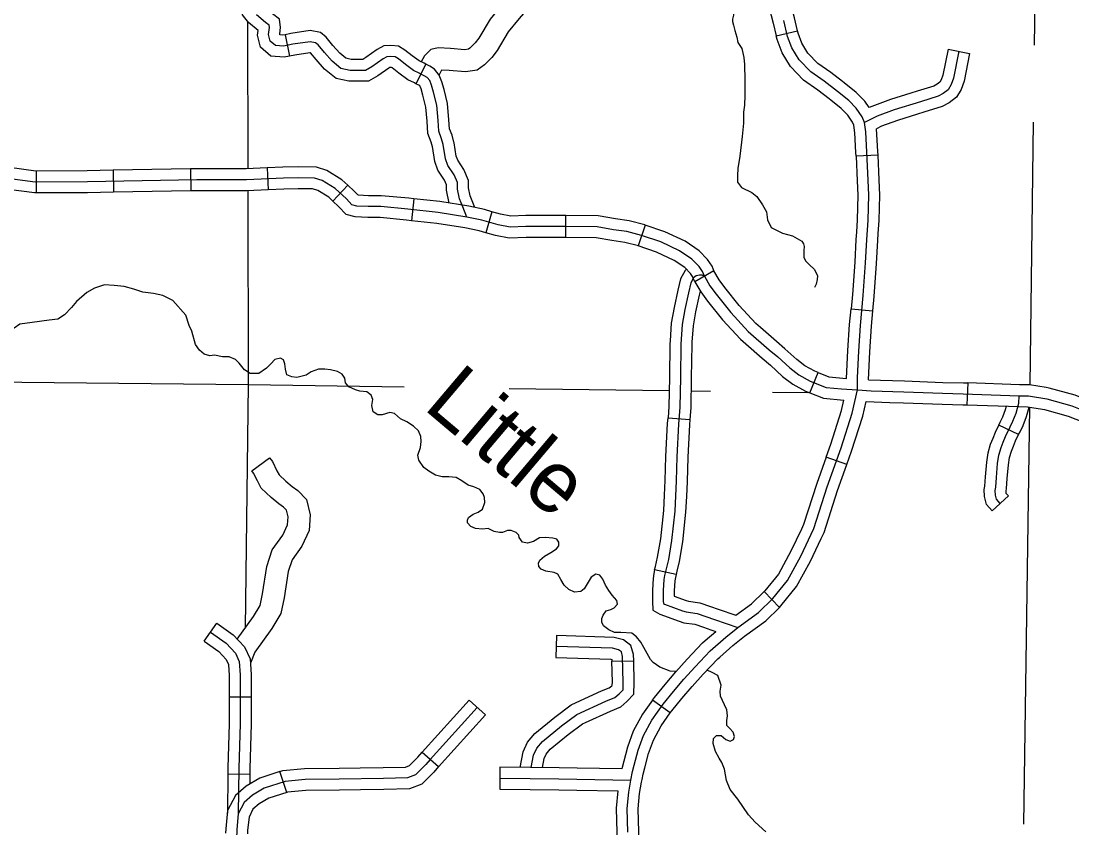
# Model space of a CAD drawing. Extents: x 813775 to 1157140, y 1757555 to 1979907.
# Drawn here: x 951173 to 965544, y 1848623 to 1859663 of the extents above; entities that cross this region are included whole.
import ezdxf

# ---------------------------------------------------------------- set-up
doc = ezdxf.new("R2010")
doc.units = 0
for name, color, linetype in [('Level 31', 7, 'Continuous'), ('Level 32', 7, 'Continuous'), ('Level 35', 7, 'Continuous'), ('Level 45', 7, 'Continuous'), ('Level 46', 7, 'Continuous'), ('Level 5', 7, 'Continuous')]:
    doc.layers.add(name, color=color, linetype=linetype)

msp = doc.modelspace()

# ---------------------------------------------------------------- linework, layer by layer
at = {"layer": 'Level 31'}
for p, q in [((961499, 1859460), (961791, 1859530)), ((963849, 1859276), (964144, 1859219)), ((962892, 1857828), (962593, 1857814)), ((962593, 1857814), (962593, 1857814)), ((960647, 1856245), (960387, 1856096)), ((962523, 1855727), (962822, 1855698)), ((961284, 1855471), (961284, 1855471)), ((961960, 1854577), (962072, 1854855)), ((964118, 1854711), (964108, 1854411)), ((965189, 1854647), (965189, 1854647)), ((960021, 1854233), (960320, 1854210)), ((962464, 1853595), (962182, 1853696)), ((960131, 1852090), (959837, 1852153)), ((959837, 1852153), (959837, 1852153)), ((961333, 1851856), (961543, 1851641)), ((959252, 1850904), (959552, 1850911)), ((959552, 1850911), (959552, 1850911)), ((960051, 1850196), (959807, 1850370)), ((959807, 1850370), (959807, 1850370)), ((956657, 1849660), (956883, 1849463)), ((957722, 1849454), (957719, 1849154)), ((954806, 1849110), (954713, 1849395)), ((954713, 1849395), (954713, 1849395))]:
    msp.add_line(p, q, dxfattribs=at)
for points in [[(961293, 1860530), (961291, 1860415), (961325, 1860214), (961379, 1859931), (961458, 1859632), (961499, 1859460)], [(961791, 1859530), (961749, 1859705), (961672, 1859998), (961620, 1860267), (961592, 1860438), (961593, 1860527)], [(962406, 1858837), (962245, 1858959), (962070, 1859083), (961934, 1859223), (961850, 1859362), (961798, 1859497), (961791, 1859530)], [(962225, 1858598), (962068, 1858717), (961874, 1858855), (961695, 1859039), (961579, 1859229), (961511, 1859409), (961499, 1859460)], [(963996, 1859248), (963925, 1858882), (963892, 1858792), (963852, 1858723), (963782, 1858670), (963713, 1858634), (963472, 1858558), (963111, 1858446), (962879, 1858362), (962709, 1858275)], [(963849, 1859276), (963780, 1858923), (963756, 1858857), (963736, 1858824), (963701, 1858797), (963656, 1858773), (963428, 1858701), (963342, 1858675)], [(964144, 1859219), (964070, 1858841), (964028, 1858728), (963967, 1858623), (963863, 1858543), (963771, 1858495), (963517, 1858415), (963431, 1858388)], [(962769, 1858481), (962710, 1858566), (962593, 1858686), (962431, 1858818), (962406, 1858837)], [(963342, 1858675), (963063, 1858589), (962769, 1858481)], [(962593, 1857814), (962590, 1857863), (962575, 1858133), (962563, 1858236), (962544, 1858279), (962478, 1858375), (962390, 1858465), (962246, 1858582), (962225, 1858598)], [(963431, 1858388), (963159, 1858304), (962939, 1858224), (962872, 1858190)], [(962892, 1857828), (962890, 1857878), (962872, 1858190)], [(962593, 1857814), (962608, 1857478), (962615, 1857278), (962606, 1856945), (962596, 1856775)], [(962896, 1856757), (962906, 1856932), (962915, 1857279), (962908, 1857490), (962892, 1857828)], [(962596, 1856775), (962590, 1856676), (962573, 1856364), (962542, 1855920), (962523, 1855727)], [(962822, 1855698), (962841, 1855895), (962872, 1856345), (962890, 1856659), (962896, 1856757)], [(960273, 1856266), (960253, 1856251), (960190, 1856136), (960154, 1855979), (960103, 1855744), (960065, 1855529), (960049, 1855287)], [(961284, 1855471), (961223, 1855525), (960994, 1855771), (960797, 1856016), (960718, 1856122), (960647, 1856245)], [(960517, 1856171), (960489, 1856184), (960451, 1856184), (960405, 1856178), (960369, 1856151), (960331, 1856082), (960300, 1855946), (960251, 1855715), (960214, 1855511), (960196, 1855242), (960189, 1854784)], [(960387, 1856096), (960467, 1855957), (960560, 1855832), (960767, 1855575), (961013, 1855310), (961086, 1855246)], [(960517, 1856171), (960592, 1856039), (960679, 1855924), (960881, 1855673), (961118, 1855417), (961405, 1855164), (961520, 1855067), (961684, 1854916), (961810, 1854821), (961966, 1854736), (962183, 1854649), (962394, 1854629), (962612, 1854618), (962798, 1854605), (963246, 1854590), (963773, 1854570), (964057, 1854563), (964821, 1854537), (964949, 1854534)], [(960459, 1855967), (960447, 1855914), (960398, 1855686), (960363, 1855492), (960348, 1855267)], [(962461, 1854774), (962479, 1855156), (962502, 1855510), (962523, 1855727)], [(962760, 1854756), (962779, 1855139), (962801, 1855486), (962822, 1855698)], [(962072, 1854855), (962030, 1854872), (961892, 1854947), (961780, 1855031), (961619, 1855180), (961503, 1855278), (961284, 1855471)], [(960049, 1855287), (960046, 1855248), (960039, 1854787), (960033, 1854387), (960021, 1854233)], [(960348, 1855267), (960346, 1855236), (960339, 1854782), (960333, 1854373), (960320, 1854210)], [(961086, 1855246), (961307, 1855050), (961421, 1854955), (961588, 1854801), (961729, 1854694), (961902, 1854600), (961960, 1854577)], [(960189, 1854784), (960183, 1854380), (960165, 1854146), (960141, 1853700), (960132, 1853371)], [(962072, 1854855), (962219, 1854797), (962461, 1854774)], [(962760, 1854756), (963252, 1854739), (963777, 1854719), (964061, 1854713), (964118, 1854711)], [(965189, 1854647), (964963, 1854684), (964826, 1854687), (964118, 1854711)], [(966222, 1854262), (966017, 1854372), (965588, 1854542), (965234, 1854640), (965189, 1854647)], [(961960, 1854577), (962147, 1854502), (962425, 1854476)], [(962182, 1853696), (962245, 1853873), (962393, 1854336), (962425, 1854476)], [(964949, 1854534), (965202, 1854493), (965541, 1854399), (965953, 1854236)], [(962464, 1853595), (962529, 1853777), (962683, 1854256), (962729, 1854457)], [(962729, 1854457), (963052, 1854446)], [(963052, 1854446), (963241, 1854440), (963768, 1854420), (964052, 1854413), (964108, 1854411)], [(964108, 1854411), (964817, 1854388), (964935, 1854384), (965141, 1854351)], [(965141, 1854351), (965170, 1854346), (965493, 1854257), (965890, 1854100), (966079, 1853998)], [(959972, 1853174), (959982, 1853376), (959991, 1853706), (960015, 1854156), (960021, 1854233)], [(960320, 1854210), (960315, 1854137), (960290, 1853694), (960282, 1853365), (960272, 1853159)], [(962182, 1853696), (962054, 1853337), (961874, 1852775), (961844, 1852712)], [(962116, 1852584), (962154, 1852665), (962338, 1853241), (962464, 1853595)], [(960132, 1853371), (960112, 1852957), (960069, 1852557), (960025, 1852297)], [(959837, 1852153), (959848, 1852202), (959878, 1852328), (959921, 1852578), (959962, 1852968), (959972, 1853174)], [(960272, 1853159), (960261, 1852945), (960218, 1852537), (960172, 1852267), (960140, 1852135), (960131, 1852090)], [(961844, 1852712), (961702, 1852410), (961529, 1852093), (961343, 1851866), (961333, 1851856)], [(961543, 1851641), (961565, 1851663), (961779, 1851925), (961970, 1852274), (962116, 1852584)], [(960025, 1852297), (959994, 1852168), (959974, 1852076), (959965, 1852020), (959956, 1851871), (959956, 1851728), (959958, 1851693), (959974, 1851684), (960220, 1851593), (960269, 1851578), (960420, 1851558), (960656, 1851476), (960973, 1851367)], [(959837, 1852153), (959827, 1852103), (959816, 1852036), (959806, 1851875), (959806, 1851724), (959814, 1851603), (959910, 1851548), (960172, 1851451), (960237, 1851431), (960385, 1851411), (960504, 1851370)], [(960131, 1852090), (960121, 1852048), (960114, 1852004), (960106, 1851866), (960106, 1851795), (960269, 1851735), (960302, 1851725), (960455, 1851704), (960603, 1851653)], [(960948, 1851534), (961162, 1851688), (961333, 1851856)], [(960603, 1851653), (960705, 1851617), (960948, 1851534)], [(960727, 1850960), (960908, 1851119), (961065, 1851248), (961356, 1851458), (961543, 1851641)], [(960504, 1851370), (960606, 1851334), (960672, 1851311)], [(960529, 1851186), (960672, 1851311)], [(959552, 1850911), (959549, 1850996), (959511, 1851121), (959413, 1851195), (959286, 1851230), (958496, 1851254), (958488, 1850954)], [(959807, 1850370), (959834, 1850409), (959980, 1850587), (960125, 1850759), (960283, 1850931), (960493, 1851154), (960529, 1851186)], [(958151, 1849450), (958182, 1849619), (958227, 1849715), (958305, 1849807), (958565, 1850021), (958775, 1850177), (959172, 1850359), (959295, 1850410), (959354, 1850460), (959405, 1850515), (959409, 1850615), (959400, 1850971), (959382, 1851031), (959345, 1851058), (959263, 1851081), (958492, 1851104)], [(958488, 1850954), (959240, 1850932), (959251, 1850929), (959252, 1850904)], [(958766, 1850338), (959112, 1850497), (959216, 1850539), (959250, 1850568), (959257, 1850576), (959259, 1850617), (959252, 1850904)], [(958891, 1850065), (959232, 1850222), (959374, 1850280), (959459, 1850352), (959552, 1850453), (959559, 1850614), (959552, 1850911)], [(960051, 1850196), (960073, 1850226), (960211, 1850395), (960350, 1850560), (960503, 1850726), (960702, 1850938), (960727, 1850960)], [(957999, 1849451), (958038, 1849666), (958100, 1849798), (958199, 1849914), (958473, 1850140), (958698, 1850306), (958766, 1850338)], [(959807, 1850370), (959671, 1850179), (959545, 1849947), (959468, 1849730), (959390, 1849431)], [(959666, 1849288), (959682, 1849359), (959704, 1849444), (959755, 1849642), (959820, 1849825), (959926, 1850020), (960051, 1850196)], [(958303, 1849448), (958326, 1849573), (958354, 1849633), (958411, 1849700), (958657, 1849903), (958852, 1850047), (958891, 1850065)], [(955811, 1849446), (956126, 1849451), (956430, 1849457), (956485, 1849478), (956598, 1849592), (956657, 1849660)], [(956770, 1849561), (956708, 1849490), (956569, 1849350), (956458, 1849308), (956129, 1849301), (955525, 1849292), (955059, 1849287), (954784, 1849261), (954500, 1849167), (954340, 1849074), (954224, 1848972), (954144, 1848816), (954122, 1848603), (954100, 1847941), (954096, 1847296)], [(954713, 1849395), (954753, 1849408), (955051, 1849437), (955524, 1849442), (955811, 1849446)], [(956883, 1849463), (956818, 1849388), (956652, 1849221), (956487, 1849159), (956132, 1849151), (955815, 1849146)], [(958779, 1849441), (958531, 1849445), (958138, 1849450), (957722, 1849454)], [(959390, 1849431), (958779, 1849441)], [(954713, 1849395), (954438, 1849305), (954251, 1849196), (954104, 1849066), (953998, 1848860), (953973, 1848613), (953971, 1848554)], [(957721, 1849304), (958136, 1849300)], [(958136, 1849300), (958528, 1849295), (959510, 1849279)], [(957719, 1849154), (958134, 1849150), (958526, 1849145), (958774, 1849141)], [(959630, 1848276), (959620, 1848569), (959611, 1848883), (959632, 1849095), (959657, 1849250), (959666, 1849288)], [(954806, 1849110), (954562, 1849030), (954428, 1848952), (954345, 1848878), (954291, 1848773), (954272, 1848593), (954270, 1848544)], [(955815, 1849146), (955527, 1849142), (955067, 1849137), (954815, 1849113), (954806, 1849110)], [(958774, 1849141), (959334, 1849132)], [(959334, 1849132), (959311, 1848893), (959320, 1848559), (959331, 1848265)]]:
    msp.add_lwpolyline(points, dxfattribs=at)
at = {"layer": 'Level 32'}
for p, q in [((953489, 1857640), (953495, 1857340)), ((954541, 1857654), (954554, 1857355)), ((951379, 1857610), (951381, 1857310)), ((952433, 1857621), (952439, 1857321)), ((955644, 1857415), (955439, 1857196)), ((956544, 1857230), (956512, 1856931)), ((957609, 1857054), (957529, 1856765)), ((958617, 1857002), (958617, 1856702)), ((959709, 1856870), (959613, 1856586)), ((964815, 1854004), (964544, 1854134)), ((964674, 1853166), (964453, 1852963)), ((953677, 1851178), (953849, 1851424)), ((954021, 1850419), (954321, 1850419)), ((957301, 1850373), (957524, 1850172)), ((954002, 1849365), (954302, 1849361))]:
    msp.add_line(p, q, dxfattribs=at)
for points in [[(956123, 1859145), (955970, 1859037), (955885, 1858988), (955801, 1858988), (955672, 1858988), (955548, 1859015), (955428, 1859113), (955322, 1859233), (955237, 1859335), (955202, 1859366), (955126, 1859380), (954891, 1859344), (954762, 1859317), (954651, 1859326), (954580, 1859388), (954558, 1859477), (954571, 1859575), (954567, 1859606), (954518, 1859642), (954394, 1859748)], [(956785, 1858785), (956762, 1858847), (956726, 1858889), (956688, 1858914), (956619, 1858949), (956539, 1858987), (956429, 1859068), (956336, 1859144), (956289, 1859173), (956227, 1859177), (956175, 1859175), (956123, 1859145)], [(957142, 1857364), (957142, 1857453), (957098, 1857559), (957009, 1857688), (956978, 1857777), (956947, 1857973), (956924, 1858053), (956885, 1858155), (956876, 1858301), (956858, 1858510), (956813, 1858688), (956785, 1858785)], [(951379, 1857610), (951375, 1857610), (951014, 1857657), (950841, 1857693), (950522, 1857821), (950424, 1857862)], [(953489, 1857640), (952433, 1857621)], [(954541, 1857654), (954253, 1857641), (953576, 1857641), (953489, 1857640)], [(955644, 1857415), (955562, 1857492), (955356, 1857616), (955213, 1857664), (954965, 1857669), (954755, 1857664), (954541, 1857654)], [(951381, 1857310), (951357, 1857310), (950964, 1857361), (950754, 1857405), (950408, 1857544), (950307, 1857586)], [(952433, 1857621), (952079, 1857614), (951379, 1857610)], [(954554, 1857355), (954260, 1857341), (953579, 1857341), (953495, 1857340)], [(955439, 1857196), (955380, 1857252), (955230, 1857342), (955161, 1857365), (954965, 1857369), (954766, 1857364), (954554, 1857355)], [(956544, 1857230), (956476, 1857237), (956100, 1857273), (955924, 1857273), (955788, 1857281), (955777, 1857284), (955728, 1857336), (955644, 1857415)], [(957269, 1856981), (957213, 1857119), (957169, 1857230), (957142, 1857364)], [(952439, 1857321), (952083, 1857314), (951381, 1857310)], [(953495, 1857340), (952439, 1857321)], [(957609, 1857054), (957510, 1857082), (957297, 1857128), (956898, 1857192), (956544, 1857230)], [(956512, 1856931), (956446, 1856938), (956085, 1856973), (955915, 1856973), (955740, 1856983), (955618, 1857016), (955516, 1857124), (955439, 1857196)], [(957529, 1856765), (957437, 1856791), (957241, 1856833), (956859, 1856894), (956512, 1856931)], [(958617, 1857002), (958074, 1857002), (957871, 1856994), (957730, 1857020), (957609, 1857054)], [(959709, 1856870), (959701, 1856873), (959488, 1856928), (959300, 1856956), (959064, 1856997), (958624, 1857002), (958617, 1857002)], [(960652, 1856236), (960624, 1856309), (960562, 1856398), (960445, 1856520), (960254, 1856649), (959976, 1856780), (959709, 1856870)], [(958617, 1856702), (958080, 1856702), (957849, 1856693), (957661, 1856728), (957529, 1856765)], [(959615, 1856586), (959429, 1856634), (959252, 1856660), (959036, 1856698), (958623, 1856702), (958617, 1856702)], [(960387, 1856096), (960357, 1856168), (960329, 1856208), (960251, 1856290), (960105, 1856387), (959863, 1856501), (959613, 1856586)], [(964545, 1853723), (964574, 1853826), (964605, 1853901), (964636, 1853980), (964699, 1854109), (964737, 1854189), (964779, 1854299), (964817, 1854435), (964821, 1854537)], [(964544, 1854134), (964563, 1854174), (964599, 1854248), (964637, 1854346), (964650, 1854393)], [(964815, 1854004), (964834, 1854044), (964875, 1854130), (964922, 1854251), (964958, 1854381)], [(964453, 1852963), (964374, 1853049), (964348, 1853158), (964344, 1853252), (964353, 1853301), (964361, 1853427), (964378, 1853626), (964398, 1853755), (964432, 1853875), (964466, 1853958), (964499, 1854040), (964544, 1854134)], [(964674, 1853166), (964648, 1853194), (964646, 1853199), (964645, 1853233), (964651, 1853266), (964660, 1853405), (964676, 1853590), (964692, 1853691), (964716, 1853776), (964744, 1853845), (964774, 1853919), (964815, 1854004)], [(964563, 1853064), (964511, 1853121), (964497, 1853178), (964495, 1853242), (964502, 1853284), (964511, 1853416), (964527, 1853608), (964545, 1853723)], [(953849, 1851424), (954075, 1851266), (954231, 1851099), (954305, 1850937), (954321, 1850722), (954321, 1850419)], [(953677, 1851178), (953877, 1851038), (953978, 1850930), (954010, 1850861), (954021, 1850711), (954021, 1850419)], [(953763, 1851301), (953976, 1851152), (954105, 1851014), (954158, 1850899), (954171, 1850717), (954171, 1850046), (954153, 1849441), (954144, 1848816)], [(954021, 1850419), (954021, 1850048), (954003, 1849444), (954002, 1849365)], [(954321, 1850419), (954321, 1850043), (954303, 1849438), (954302, 1849361)], [(957301, 1850373), (956659, 1849662)], [(957412, 1850272), (956770, 1849561)], [(957524, 1850172), (956882, 1849461)], [(954002, 1849365), (953995, 1848825)], [(954302, 1849361), (954300, 1849225)]]:
    msp.add_lwpolyline(points, dxfattribs=at)
at = {"layer": 'Level 35'}
for points in [[(960761, 1860032), (960811, 1859912), (960883, 1859848), (960920, 1859795), (960918, 1859742), (960902, 1859689), (960904, 1859657), (960915, 1859604), (960936, 1859535), (960963, 1859441), (960973, 1859370), (961029, 1859285), (961056, 1859162), (961066, 1859067)], [(961066, 1859067), (961072, 1858855), (961072, 1858738), (961069, 1858645), (961066, 1858512), (961053, 1858416), (961053, 1858265), (961035, 1858082)], [(961035, 1858082), (961003, 1857815), (960973, 1857647), (960971, 1857549), (960971, 1857456), (961024, 1857387), (961165, 1857315), (961234, 1857264), (961313, 1857150), (961366, 1857052), (961382, 1856943), (961430, 1856839), (961584, 1856762), (961722, 1856722)], [(961722, 1856722), (961818, 1856670), (961852, 1856649), (961873, 1856614), (961884, 1856580), (961879, 1856524), (961879, 1856471), (961876, 1856431), (961900, 1856383), (961956, 1856327), (962020, 1856269), (962035, 1856237), (962065, 1856178), (962062, 1856125), (962046, 1856061), (962022, 1856016)], [(953251, 1855839), (953111, 1855909), (952983, 1855935), (952840, 1855955), (952714, 1855992), (952585, 1856032), (952445, 1856044), (952314, 1856052), (952180, 1856007), (952071, 1855947), (951931, 1855826), (951862, 1855743), (951768, 1855643), (951676, 1855586), (951556, 1855572)], [(955071, 1854819), (954943, 1854786), (954877, 1854795), (954809, 1854824), (954791, 1854901), (954780, 1854975), (954760, 1855027), (954723, 1855050), (954646, 1855030), (954589, 1854972), (954531, 1854915), (954423, 1854841), (954306, 1854841), (954228, 1854892), (954154, 1854981), (954108, 1855032), (954020, 1855067), (953928, 1855070), (953820, 1855093), (953754, 1855084), (953677, 1855104), (953614, 1855161), (953560, 1855238), (953511, 1855419), (953474, 1855499), (953425, 1855639), (953251, 1855839)], [(951556, 1855572), (951326, 1855540), (951157, 1855515), (951080, 1855460), (950954, 1855389), (950806, 1855297), (950697, 1855289), (950563, 1855326), (950446, 1855409), (950357, 1855497), (950294, 1855526), (950123, 1855549), (949943, 1855549), (949574, 1855466), (949425, 1855392)], [(956597, 1853725), (956634, 1853826), (956643, 1853912), (956640, 1853978), (956609, 1854055), (956540, 1854121), (956451, 1854178), (956363, 1854221), (956280, 1854295), (956217, 1854307), (956111, 1854273), (956051, 1854273), (955988, 1854315), (955971, 1854401), (955983, 1854484), (955963, 1854542), (955900, 1854590), (955808, 1854599), (955745, 1854619), (955657, 1854656), (955608, 1854713), (955600, 1854776), (955565, 1854830), (955502, 1854868), (955405, 1854891), (955328, 1854899), (955239, 1854902), (955139, 1854865), (955071, 1854819)], [(957422, 1852944), (957485, 1852984), (957517, 1853076), (957511, 1853144), (957491, 1853196), (957445, 1853253), (957365, 1853290), (957288, 1853313), (957203, 1853373), (957125, 1853416), (957022, 1853425), (956931, 1853427), (956842, 1853450), (956751, 1853505), (956682, 1853556), (956611, 1853653), (956597, 1853725)], [(958351, 1852135), (958285, 1852163), (958254, 1852198), (958251, 1852246), (958268, 1852286), (958331, 1852341), (958420, 1852392), (958494, 1852441), (958525, 1852484), (958528, 1852532), (958502, 1852573), (958445, 1852590), (958342, 1852595), (958265, 1852593), (958179, 1852541), (958099, 1852518), (958031, 1852532), (957985, 1852595), (957982, 1852627), (957942, 1852667), (957877, 1852693), (957825, 1852693), (957759, 1852664), (957716, 1852664), (957642, 1852678), (957562, 1852718), (957482, 1852710), (957388, 1852718), (957322, 1852747), (957279, 1852796), (957279, 1852833), (957291, 1852870), (957356, 1852916), (957422, 1852944)], [(959176, 1851593), (959240, 1851612), (959283, 1851635), (959329, 1851687), (959320, 1851733), (959257, 1851810), (959211, 1851873), (959166, 1851944), (959131, 1852027), (959088, 1852082), (959031, 1852093), (958971, 1852056), (958914, 1851964), (958874, 1851896), (958828, 1851856), (958740, 1851850), (958663, 1851884), (958600, 1851947), (958554, 1852024), (958514, 1852093), (958465, 1852119), (958351, 1852135)], [(960131, 1850765), (960048, 1850767), (959908, 1850821), (959819, 1850887), (959779, 1850930), (959691, 1851090), (959648, 1851164), (959588, 1851236), (959525, 1851287), (959373, 1851296), (959288, 1851299), (959213, 1851333), (959136, 1851390), (959116, 1851439), (959113, 1851490), (959133, 1851533), (959176, 1851593)], [(960748, 1850576), (960700, 1850709), (960625, 1850752), (960556, 1850783)], [(960639, 1849777), (960643, 1849846), (960685, 1849886), (960748, 1849886), (960811, 1849832), (960868, 1849809), (960914, 1849832), (960928, 1849875), (960911, 1849935), (960860, 1849989), (960825, 1850027), (960825, 1850095), (960834, 1850158), (960825, 1850238), (960791, 1850307), (960740, 1850424), (960734, 1850496), (960748, 1850576)], [(961357, 1848568), (961214, 1848701), (961122, 1848804), (960974, 1849016), (960871, 1849150), (960819, 1849273), (960791, 1849428), (960756, 1849519), (960722, 1849579), (960668, 1849668), (960639, 1849777)]]:
    msp.add_lwpolyline(points, dxfattribs=at)
at = {"layer": 'Level 45'}
for p, q in [((954783, 1859475), (954844, 1859181)), ((956709, 1859072), (956571, 1858805))]:
    msp.add_line(p, q, dxfattribs=at)
for points in [[(954844, 1859181), (954772, 1859166), (954590, 1859181), (954446, 1859307), (954405, 1859469), (954414, 1859533), (954285, 1859644), (954201, 1859749), (954174, 1859876), (954163, 1860044), (954174, 1860106)], [(954783, 1859475), (954753, 1859469), (954714, 1859472), (954710, 1859486), (954723, 1859576), (954706, 1859690), (954611, 1859760), (954502, 1859853), (954479, 1859881), (954471, 1859918), (954465, 1860026), (954469, 1860052)], [(955712, 1859138), (955688, 1859138), (955615, 1859154), (955532, 1859222), (955436, 1859330), (955345, 1859440), (955269, 1859507), (955128, 1859532), (954864, 1859492), (954783, 1859475)], [(955712, 1858838), (955656, 1858838), (955481, 1858876), (955324, 1859004), (955208, 1859135), (955133, 1859226), (955124, 1859228), (954917, 1859196), (954844, 1859181)], [(956709, 1859072), (956685, 1859084), (956616, 1859117), (956521, 1859186), (956423, 1859266), (956337, 1859320), (956229, 1859327), (956132, 1859323), (956043, 1859272), (955889, 1859164), (955845, 1859138), (955801, 1859138), (955712, 1859138)], [(957095, 1857994), (957093, 1858004), (957067, 1858100), (957033, 1858187), (957025, 1858312), (957006, 1858535), (956958, 1858727), (956928, 1858833), (956893, 1858924), (956826, 1859003), (956763, 1859044), (956709, 1859072)], [(956571, 1858805), (956552, 1858815), (956461, 1858858), (956338, 1858949), (956249, 1859021), (956241, 1859026), (956224, 1859027), (956218, 1859027), (956204, 1859018), (956051, 1858911), (955926, 1858838), (955801, 1858838), (955712, 1858838)], [(956800, 1857941), (956782, 1858005), (956736, 1858122), (956726, 1858291), (956709, 1858486), (956669, 1858649), (956643, 1858737), (956631, 1858769), (956626, 1858775), (956613, 1858784), (956571, 1858805)], [(954257, 1857491), (953577, 1857491), (952081, 1857464), (951366, 1857460), (950989, 1857509), (950798, 1857549), (950465, 1857682), (950087, 1857842), (949563, 1858118), (949062, 1858313), (948737, 1858416), (948321, 1858502)], [(957028, 1857171), (956992, 1857349), (956992, 1857423), (956965, 1857487), (956874, 1857620), (956832, 1857740), (956799, 1857947)], [(957378, 1857111), (957313, 1857273), (957292, 1857379), (957292, 1857483), (957230, 1857631), (957144, 1857757), (957124, 1857814), (957095, 1857994)], [(959458, 1856781), (959276, 1856808), (959050, 1856848), (958624, 1856852), (958077, 1856852), (957860, 1856843), (957696, 1856874), (957474, 1856936), (957269, 1856981), (956879, 1857043), (956461, 1857088), (956093, 1857123), (955919, 1857123), (955764, 1857132), (955697, 1857150), (955622, 1857230), (955471, 1857372), (955293, 1857479), (955187, 1857514), (954965, 1857519), (954761, 1857514), (954257, 1857491)], [(960517, 1856171), (960490, 1856238), (960446, 1856303), (960348, 1856405), (960179, 1856518), (959920, 1856640), (959658, 1856729), (959458, 1856781)]]:
    msp.add_lwpolyline(points, dxfattribs=at)
at = {"layer": 'Level 46'}
for points in [[(958126, 1860182), (958103, 1860142), (958083, 1860118), (958066, 1860103), (958051, 1860094), (958006, 1860083), (957928, 1860062), (957869, 1860018), (957822, 1859971), (957752, 1859889), (957588, 1859687), (957433, 1859427), (957385, 1859363), (957311, 1859290), (957293, 1859276), (957244, 1859270), (957046, 1859287), (956875, 1859294), (956777, 1859271), (956689, 1859188), (956645, 1859103)], [(958385, 1860029), (958350, 1859971), (958298, 1859906), (958240, 1859858), (958166, 1859813), (958081, 1859793), (958063, 1859788), (958043, 1859767), (957983, 1859697), (957835, 1859515), (957682, 1859258), (957610, 1859165), (957510, 1859064), (957412, 1858989), (957251, 1858968), (957026, 1858987), (956925, 1858992), (956892, 1858926)], [(962612, 1854618), (962611, 1854785), (962629, 1855147), (962651, 1855498), (962691, 1855907), (962722, 1856354), (962740, 1856668), (962756, 1856939), (962765, 1857279), (962758, 1857484), (962740, 1857870), (962725, 1858146), (962709, 1858275), (962676, 1858353), (962594, 1858470), (962492, 1858576), (962338, 1858700), (962156, 1858838), (961972, 1858969), (961814, 1859131), (961715, 1859295), (961655, 1859453), (961604, 1859669)], [(960973, 1851367), (961259, 1851573), (961454, 1851764), (961654, 1852009), (961836, 1852342), (962014, 1852720), (962196, 1853289), (962387, 1853825), (962538, 1854296), (962612, 1854618)], [(954331, 1853508), (954571, 1853688), (954610, 1853636), (954673, 1853511), (954701, 1853456), (954796, 1853366), (954879, 1853295), (954957, 1853241), (955076, 1853116), (955126, 1852905), (955114, 1852694), (955012, 1852478), (954880, 1852290), (954828, 1852132), (954772, 1851771), (954726, 1851556), (954603, 1851351), (954370, 1851028), (954310, 1850876)], [(954130, 1851207), (954352, 1851516), (954443, 1851667), (954476, 1851825), (954535, 1852202), (954608, 1852426), (954752, 1852629), (954818, 1852769), (954824, 1852878), (954803, 1852969), (954761, 1853012), (954697, 1853056), (954595, 1853143), (954458, 1853274), (954406, 1853374), (954354, 1853477), (954331, 1853508)], [(959470, 1848564), (959461, 1848888), (959483, 1849115), (959510, 1849279), (959536, 1849395), (959558, 1849482), (959612, 1849686), (959683, 1849886), (959798, 1850100), (959954, 1850317), (960096, 1850491), (960238, 1850660), (960393, 1850828), (960597, 1851046), (960811, 1851233), (960973, 1851367)]]:
    msp.add_lwpolyline(points, dxfattribs=at)
at = {"layer": 'Level 5'}
for points in [[(965040, 1860258), (965028, 1859331)], [(954270, 1859657), (954273, 1857642)], [(965015, 1858280), (964969, 1854683)], [(954273, 1857342), (954277, 1854688)], [(943663, 1854801), (954277, 1854688)], [(954277, 1854688), (954236, 1851355)], [(954277, 1854688), (956413, 1854658)], [(957846, 1854637), (960036, 1854606)], [(960336, 1854602), (960601, 1854599)], [(961448, 1854587), (961931, 1854580)], [(964965, 1854379), (964880, 1848677)]]:
    msp.add_lwpolyline(points, dxfattribs=at)

# ---------------------------------------------------------------- texts
at = {"layer": 'Level 35'}
msp.add_text('Little', height=844.8, rotation=319.78, dxfattribs=at).set_placement((956658, 1854368))

doc.saveas('drawing.dxf')
